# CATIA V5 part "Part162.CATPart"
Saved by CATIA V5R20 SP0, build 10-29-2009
Part number: DFA 084700-2 comprimido
Revision: ANY
Definition: UNKNOWN
Nomenclature: DFA 084700-2 comprimido
Source: Unknown
Bounding box of the stored display mesh (mm): x -2.45 to 2.45, y 0 to 4.72, z -2.45 to 2.45
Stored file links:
  C:\Users\Utente\Desktop\IO LAVORO\3D X SITO CF\CUMSA\3D files FA\FA 105712-21\Part162.CATPart
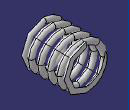
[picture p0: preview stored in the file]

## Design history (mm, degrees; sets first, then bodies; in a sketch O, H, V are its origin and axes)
Body1 "Cortar-Extruir1" (main body)
  Solid1: solid without history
